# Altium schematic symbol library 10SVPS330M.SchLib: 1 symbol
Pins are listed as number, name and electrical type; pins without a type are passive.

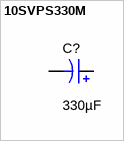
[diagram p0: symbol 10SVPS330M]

## 10SVPS330M
designator C?  ValueDisplayed: 330µF  (hidden comment: 10SVPS330M)
CAP, AL, 330uF, 10V, +/-20%, SMD; Manufacturer: Panasonic; Polarized: Y; CompType: Capacitor; U/M: EA; Cap_F: 0.00033; Tolerance_%: 20; VDC_V: 25; Value2: 25V; IRMS_A: 0.6; TaMin_C: -55; TaMax_C: 105; Cap_Case: HA0
signal-integrity model Cap
simulation model Cap
footprint SVPS_F8 (PANASONIC SVPS_F8)
pins: 1 +, 2 -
